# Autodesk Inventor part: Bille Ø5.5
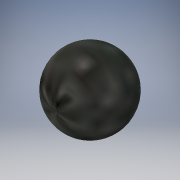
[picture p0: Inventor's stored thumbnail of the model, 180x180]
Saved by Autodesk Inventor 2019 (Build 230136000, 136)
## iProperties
Created: 2018-06
Part Number: Bille Ø5.5
Material: Acier
Document SubType Name: Modeling
Designer: Fabian Perrée
Density: 7.85 g/cm^3
Appearance: Plaque
Author: Fabian Perrée
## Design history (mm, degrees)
sketch "Esquisse1"
  geometry: L1 (0, 2.75)-(0, -2.75); A1 r 2.75 centre (0, 0) between (0, -2.75) and (0, 2.75); 2 further points
  constraints: 2 coincident, 2 end point, 2 point on circle, 1 centre point, 1 midpoint, 1 vertical
  dimensions: "d2" = 2.75 radius of A1
revolve "Révolution1" sketch "Esquisse1" stored, may be unused: angle "d3" = 90 deg
node "Solide1"
